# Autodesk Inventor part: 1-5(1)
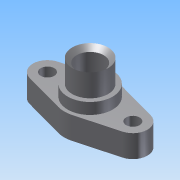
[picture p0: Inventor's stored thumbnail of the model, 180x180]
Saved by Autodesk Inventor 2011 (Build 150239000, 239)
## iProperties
Created: 2014-01
Part Number: 1-5(1)
Document SubType Name: Modeling
Designer: Administrator
Density: 1 g/cm^3
Author: Administrator
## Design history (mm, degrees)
sketch "草图1"
  geometry: L1 (-3.026, 11.095)-(-20.711, 6.271); L2 (-3.026, -11.095)-(-20.711, -6.271); L3 (3.026, 11.095)-(20.711, 6.271); L4 (3.026, -11.095)-(20.711, -6.271); L5 (0, 20.184)-(0, -27.309); A1 r 6.5 centre (-19, 0) between (-20.711, 6.271) and (-20.711, -6.271); A2 r 6.5 centre (19, 0) between (20.711, -6.271) and (20.711, 6.271); A3 r 11.5 centre (0, 0) between (-3.026, -11.095) and (3.026, -11.095); A4 r 11.5 centre (0, 0) between (3.026, 11.095) and (-3.026, 11.095); 1 further point
  constraints: 10 end point, 8 point on circle, 8 tangent, 4 centre point, 2 horizontal alignment, 1 coincident, 1 symmetric about line, 1 vertical, 1 vertical alignment
  dimensions: "d2" = 13 diameter of A1; "d4" = 13 diameter of A2; "d43" = 38 distance of A2.centre A1.centre
extrude "拉伸1" new body sketch "草图1" distance "d5" = 10; taper "d6" = 0 deg
sketch "草图2"
  geometry: C1 r 10 at (0, 0); 1 further point
  constraints: 1 centre point, 1 coincident
extrude "拉伸2" join sketch "草图2" distance "d7" = 5; taper "d8" = 0 deg
sketch "草图3"
  geometry: C1 r 10 at (0, 0) reference; C2 r 8 at (0, 0)
  constraints: 1 centre point, 1 coincident
  dimensions: "d9" = 16 diameter of C2
extrude "拉伸3" join sketch "草图3" distance "d10" = 10; taper "d11" = 0 deg
sketch "草图4"
  geometry: C1 r 8 at (0, 0); 1 further point
  constraints: 1 centre point, 1 coincident
  dimensions: "d12" = 16 diameter of C1
extrude "拉伸4" cut sketch "草图4" distance "d13" = 3; taper "d14" = 0 deg
sketch "草图5"
  geometry: C1 r 8 at (0, 0) reference; C2 r 6 at (0, 0)
  constraints: 1 centre point, 1 coincident
  dimensions: "d15" = 12 diameter of C2
extrude "拉伸5" cut sketch "草图5" stored distance "d16" = 3; taper "d17" = 0 deg
chamfer "倒角1" distance "d18" = 2; stored, may be unused: second distance "d19" = 2, angle "d20" = 45 deg
sketch "草图6"
  geometry: C1 r 5 at (-19, 0); C2 r 5 at (19, 0); A1 r 6.5 centre (-19, 0) between (-20.711, 6.271) and (-20.711, -6.271) reference; A2 r 6.5 centre (19, 0) between (20.711, -6.271) and (20.711, 6.271) reference
  constraints: 2 centre point, 2 coincident
  dimensions: "d21" = 10 diameter of C1; "d22" = 10 diameter of C2
extrude "拉伸6" cut sketch "草图6" distance "d23" = 4; taper "d24" = 0 deg
hole "Hole1" diameter "d27" = 6; stored, may be unused: countersink angle "d31" = 90 deg, drill point angle "d33" = 0 deg; dims "d25" = 10, "d26" = 10, "d28" = 6, "d29" = 4, "d30" = 2, "d32" = 6
hole "Hole2" diameter "d36" = 6; stored, may be unused: countersink angle "d40" = 90 deg, drill point angle "d42" = 118 deg; dims "d34" = 10, "d35" = 10, "d37" = 6, "d38" = 4, "d39" = 2, "d41" = 6
node "实体1"
other parameters: "d44" = 23
